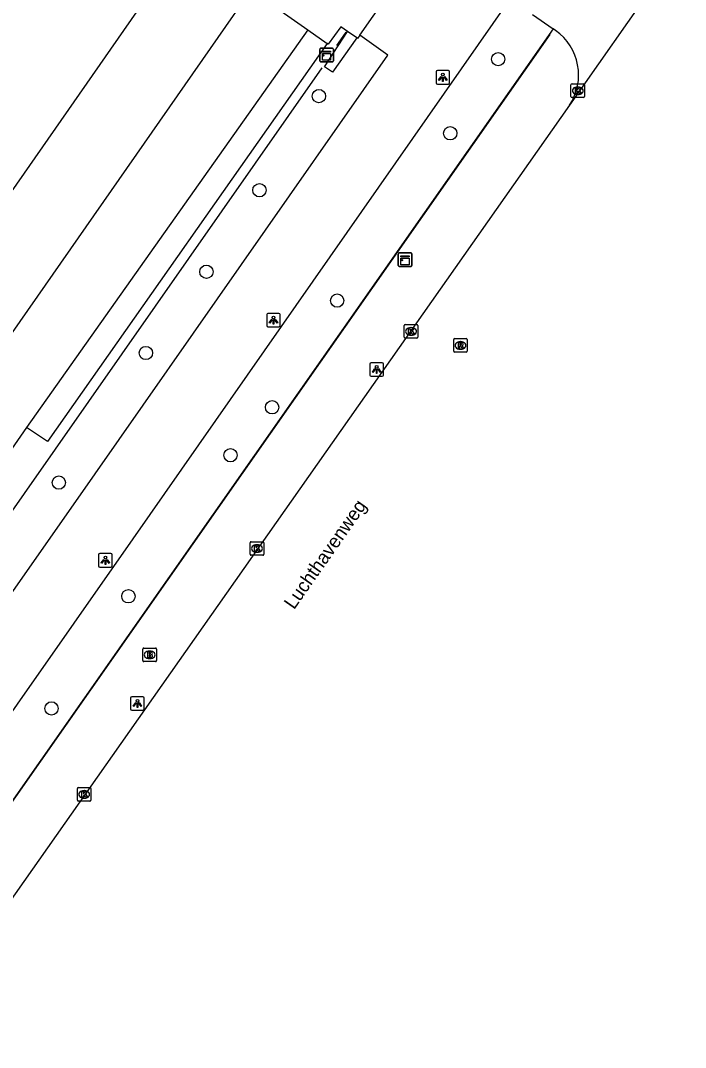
# Model space of a CAD drawing. Extents: x 152881 to 155736, y 382924 to 386919.
# Drawn here: x 155113.9 to 155162.7, y 385052.2 to 385127.6 of the extents above; entities that cross this region are included whole.
import ezdxf

# ---------------------------------------------------------------- set-up
doc = ezdxf.new("R2010")
doc.units = 0
for name, color, linetype in [('IMGEO_Berm_groen', 7, 'Continuous'), ('IMGEO_Boom', 7, 'Continuous'), ('IMGEO_Brandkraan', 7, 'Continuous'), ('IMGEO_Hek', 7, 'Continuous'), ('IMGEO_Kast', 7, 'Continuous'), ('IMGEO_Kolk', 7, 'Continuous'), ('IMGEO_Lichtpunt', 7, 'Continuous'), ('IMGEO_Openbare_ruimte_label', 7, 'Continuous'), ('IMGEO_Parkeervlak_gesloten', 7, 'Continuous'), ('IMGEO_Rijbaan_lokaal_gesloten', 7, 'Continuous'), ('IMGEO_Rijbaan_lokaal_open', 7, 'Continuous'), ('IMGEO_Rioolput', 7, 'Continuous'), ('IMGEO_Voetpad_gesloten', 7, 'Continuous'), ('IMGEO_Voetpad_halfverhard', 7, 'Continuous'), ('IMGEO_Voetpad_open', 7, 'Continuous')]:
    doc.layers.add(name, color=color, linetype=linetype)

msp = doc.modelspace()

# ---------------------------------------------------------------- linework, layer by layer
at = {"layer": 'IMGEO_Berm_groen'}
msp.add_lwpolyline([(155152.981, 385126.958), (155077.878, 385019.794)], dxfattribs=at)
at = {"layer": 'IMGEO_Boom'}
for centre in [(155148.933, 385124.732), (155135.772, 385122.021), (155145.413, 385119.287), (155131.404, 385115.109), (155127.505, 385109.119), (155137.113, 385107.003), (155123.064, 385103.156), (155132.332, 385099.167), (155129.278, 385095.648), (155116.668, 385093.637), (155121.775, 385085.29), (155116.13, 385077.056)]:
    msp.add_circle(centre, 0.489, dxfattribs=at)
at = {"layer": 'IMGEO_Brandkraan'}
for p, q in [((155122.917, 385081.491), (155123.769, 385081.491)), ((155122.842, 385080.565), (155122.842, 385081.417)), ((155123.353, 385080.711), (155123.328, 385080.711)), ((155123.33, 385081.271), (155123.355, 385081.271)), ((155123.843, 385081.417), (155123.843, 385080.565)), ((155123.769, 385080.491), (155122.917, 385080.491))]:
    msp.add_line(p, q, dxfattribs=at)
for points in [[(155122.917, 385081.491), (155123.769, 385081.491)], [(155122.842, 385080.565), (155122.842, 385081.417)], [(155123.19, 385081.191), (155123.19, 385080.791), (155123.403, 385080.791)], [(155123.421, 385081.191), (155123.19, 385081.191)], [(155123.369, 385081.11), (155123.315, 385081.11), (155123.315, 385081.034)], [(155123.315, 385081.034), (155123.368, 385081.034)], [(155123.377, 385080.958), (155123.315, 385080.958), (155123.315, 385080.877)], [(155123.315, 385080.877), (155123.377, 385080.877)], [(155123.843, 385081.417), (155123.843, 385080.565)], [(155123.769, 385080.491), (155122.917, 385080.491)]]:
    msp.add_lwpolyline(points, dxfattribs=at)
for centre, radius, start, end in [((155122.919, 385081.415), 0.0765, 91.55205, 178.44795), ((155122.919, 385081.415), 0.0765, 91.55205, 178.44795), ((155123.767, 385081.415), 0.0765, 1.55205, 88.44795), ((155123.767, 385081.415), 0.0765, 1.55205, 88.44795), ((155123.37, 385081.072), 0.0379, 267.82845, 90.93552), ((155123.378, 385080.917), 0.0404, 269.87594, 90.50774), ((155123.409, 385081.042), 0.251, 268.66757, 293.53466), ((155123.425, 385081.046), 0.145, 59.4692, 91.53667), ((155123.45, 385081.093), 0.0922, 285.51372, 58.15012), ((155123.455, 385080.901), 0.105, 301.31148, 78.98903), ((155122.919, 385080.567), 0.0765, 181.55205, 268.44795), ((155122.919, 385080.567), 0.0765, 181.55205, 268.44795), ((155123.767, 385080.567), 0.0765, 271.55205, 358.44795), ((155123.767, 385080.567), 0.0765, 271.55205, 358.44795)]:
    msp.add_arc(centre, radius, start, end, dxfattribs=at)
for centre, major_axis, ratio, start_param, end_param in [((155123.329, 385080.991), (-0.387, 0.002), 0.722429, 4.712389, 7.853982), ((155123.354, 385080.991), (-0.39, 0.002), 0.717154, 1.570796, 4.712389)]:
    msp.add_ellipse(centre, major_axis=major_axis, ratio=ratio, start_param=start_param, end_param=end_param, dxfattribs=at)
at = {"layer": 'IMGEO_Hek'}
for points in [[(155137.751, 385126.715), (155137.058, 385125.724)], [(155152.718, 385126.532), (155081.57, 385025.069)], [(155094.545, 385064.824), (155135.997, 385124.094)]]:
    msp.add_lwpolyline(points, dxfattribs=at)
at = {"layer": 'IMGEO_Kast'}
for p, q in [((155135.832, 385124.612), (155135.832, 385125.453)), ((155135.832, 385125.453), (155135.832, 385124.612)), ((155135.907, 385125.537), (155136.748, 385125.537)), ((155136.748, 385125.537), (155135.907, 385125.537)), ((155136.832, 385125.462), (155136.832, 385124.621)), ((155136.832, 385124.621), (155136.832, 385125.462)), ((155136.757, 385124.537), (155135.916, 385124.537)), ((155135.916, 385124.537), (155136.757, 385124.537)), ((155141.599, 385109.583), (155141.599, 385110.424)), ((155141.599, 385110.424), (155141.599, 385109.583)), ((155141.674, 385110.508), (155142.515, 385110.508)), ((155142.515, 385110.508), (155141.674, 385110.508)), ((155142.599, 385110.433), (155142.599, 385109.592)), ((155142.599, 385109.592), (155142.599, 385110.433)), ((155142.524, 385109.508), (155141.683, 385109.508)), ((155141.683, 385109.508), (155142.524, 385109.508))]:
    msp.add_line(p, q, dxfattribs=at)
for points in [[(155136.027, 385125.327), (155136.627, 385125.327), (155136.627, 385125.242), (155136.027, 385125.242), (155136.027, 385125.327)], [(155136.027, 385125.152), (155136.627, 385125.152), (155136.627, 385124.663), (155136.027, 385124.663), (155136.027, 385125.152)], [(155141.794, 385110.298), (155142.394, 385110.298), (155142.394, 385110.213), (155141.794, 385110.213), (155141.794, 385110.298)], [(155141.794, 385110.123), (155142.394, 385110.123), (155142.394, 385109.634), (155141.794, 385109.634), (155141.794, 385110.123)]]:
    msp.add_lwpolyline(points, dxfattribs=at)
for centre in [(155136.111, 385125.001), (155141.878, 385109.972)]:
    msp.add_circle(centre, 0.0377, dxfattribs=at)
for centre, start, end in [((155135.91, 385125.459), 92.4484, 184.28452), ((155135.91, 385125.459), 92.4484, 184.28452), ((155136.754, 385125.459), 2.4484, 94.28452), ((155136.754, 385125.459), 2.4484, 94.28452), ((155135.91, 385124.615), 182.4484, 274.28452), ((155135.91, 385124.615), 182.4484, 274.28452), ((155136.754, 385124.615), 272.4484, 4.28452), ((155136.754, 385124.615), 272.4484, 4.28452), ((155141.677, 385110.43), 92.4484, 184.28452), ((155141.677, 385110.43), 92.4484, 184.28452), ((155142.521, 385110.43), 2.4484, 94.28452), ((155142.521, 385110.43), 2.4484, 94.28452), ((155141.677, 385109.586), 182.4484, 274.28452), ((155141.677, 385109.586), 182.4484, 274.28452), ((155142.521, 385109.586), 272.4484, 4.28452), ((155142.521, 385109.586), 272.4484, 4.28452)]:
    msp.add_arc(centre, 0.0779, start, end, dxfattribs=at)
at = {"layer": 'IMGEO_Kolk'}
for p, q in [((155154.283, 385121.991), (155154.283, 385122.843)), ((155154.358, 385122.917), (155155.21, 385122.917)), ((155154.771, 385122.697), (155154.796, 385122.697)), ((155155.284, 385122.843), (155155.284, 385121.991)), ((155155.21, 385121.917), (155154.358, 385121.917)), ((155154.794, 385122.137), (155154.769, 385122.137)), ((155142.036, 385104.313), (155142.036, 385105.165)), ((155142.111, 385105.239), (155142.963, 385105.239)), ((155142.524, 385105.019), (155142.549, 385105.019)), ((155143.037, 385105.165), (155143.037, 385104.313)), ((155142.963, 385104.239), (155142.111, 385104.239)), ((155142.547, 385104.459), (155142.522, 385104.459)), ((155130.72, 385088.374), (155130.72, 385089.226)), ((155130.795, 385089.3), (155131.647, 385089.3)), ((155131.208, 385089.08), (155131.233, 385089.08)), ((155131.721, 385089.226), (155131.721, 385088.374)), ((155131.647, 385088.3), (155130.795, 385088.3)), ((155131.231, 385088.52), (155131.206, 385088.52)), ((155118.029, 385070.319), (155118.029, 385071.171)), ((155118.104, 385071.245), (155118.956, 385071.245)), ((155118.517, 385071.025), (155118.542, 385071.025)), ((155119.03, 385071.171), (155119.03, 385070.319)), ((155118.956, 385070.245), (155118.104, 385070.245)), ((155118.54, 385070.465), (155118.515, 385070.465))]:
    msp.add_line(p, q, dxfattribs=at)
for points in [[(155154.283, 385121.991), (155154.283, 385122.843)], [(155154.358, 385122.917), (155155.21, 385122.917)], [(155154.604, 385122.617), (155154.727, 385122.617), (155154.727, 385122.466), (155154.857, 385122.617), (155155.021, 385122.617), (155154.875, 385122.466), (155155.028, 385122.217), (155154.876, 385122.217), (155154.791, 385122.381), (155154.727, 385122.314), (155154.727, 385122.217), (155154.604, 385122.217), (155154.604, 385122.617)], [(155155.284, 385122.843), (155155.284, 385121.991)], [(155155.21, 385121.917), (155154.358, 385121.917)], [(155142.036, 385104.313), (155142.036, 385105.165)], [(155142.111, 385105.239), (155142.963, 385105.239)], [(155142.357, 385104.939), (155142.48, 385104.939), (155142.48, 385104.788), (155142.61, 385104.939), (155142.774, 385104.939), (155142.628, 385104.788), (155142.781, 385104.539), (155142.629, 385104.539), (155142.544, 385104.703), (155142.48, 385104.636), (155142.48, 385104.539), (155142.357, 385104.539), (155142.357, 385104.939)], [(155143.037, 385105.165), (155143.037, 385104.313)], [(155142.963, 385104.239), (155142.111, 385104.239)], [(155130.72, 385088.374), (155130.72, 385089.226)], [(155130.795, 385089.3), (155131.647, 385089.3)], [(155131.721, 385089.226), (155131.721, 385088.374)], [(155131.647, 385088.3), (155130.795, 385088.3)], [(155131.041, 385089), (155131.164, 385089), (155131.164, 385088.849), (155131.294, 385089), (155131.458, 385089), (155131.312, 385088.849), (155131.465, 385088.6), (155131.313, 385088.6), (155131.228, 385088.764), (155131.164, 385088.697), (155131.164, 385088.6), (155131.041, 385088.6), (155131.041, 385089)], [(155118.029, 385070.319), (155118.029, 385071.171)], [(155118.104, 385071.245), (155118.956, 385071.245)], [(155118.35, 385070.945), (155118.473, 385070.945), (155118.473, 385070.794), (155118.603, 385070.945), (155118.767, 385070.945), (155118.621, 385070.794), (155118.774, 385070.545), (155118.622, 385070.545), (155118.537, 385070.709), (155118.473, 385070.642), (155118.473, 385070.545), (155118.35, 385070.545), (155118.35, 385070.945)], [(155119.03, 385071.171), (155119.03, 385070.319)], [(155118.956, 385070.245), (155118.104, 385070.245)]]:
    msp.add_lwpolyline(points, dxfattribs=at)
for centre, start, end in [((155154.36, 385122.841), 91.55205, 178.44795), ((155154.36, 385122.841), 91.55205, 178.44795), ((155155.208, 385122.841), 1.55205, 88.44795), ((155155.208, 385122.841), 1.55205, 88.44795), ((155154.36, 385121.993), 181.55205, 268.44795), ((155154.36, 385121.993), 181.55205, 268.44795), ((155155.208, 385121.993), 271.55205, 358.44795), ((155155.208, 385121.993), 271.55205, 358.44795), ((155142.113, 385105.163), 91.55205, 178.44795), ((155142.113, 385105.163), 91.55205, 178.44795), ((155142.961, 385105.163), 1.55205, 88.44795), ((155142.961, 385105.163), 1.55205, 88.44795), ((155142.113, 385104.315), 181.55205, 268.44795), ((155142.113, 385104.315), 181.55205, 268.44795), ((155142.961, 385104.315), 271.55205, 358.44795), ((155142.961, 385104.315), 271.55205, 358.44795), ((155130.797, 385089.224), 91.55205, 178.44795), ((155130.797, 385089.224), 91.55205, 178.44795), ((155131.645, 385089.224), 1.55205, 88.44795), ((155131.645, 385089.224), 1.55205, 88.44795), ((155130.797, 385088.376), 181.55205, 268.44795), ((155130.797, 385088.376), 181.55205, 268.44795), ((155131.645, 385088.376), 271.55205, 358.44795), ((155131.645, 385088.376), 271.55205, 358.44795), ((155118.106, 385071.169), 91.55205, 178.44795), ((155118.106, 385071.169), 91.55205, 178.44795), ((155118.954, 385071.169), 1.55205, 88.44795), ((155118.954, 385071.169), 1.55205, 88.44795), ((155118.106, 385070.321), 181.55205, 268.44795), ((155118.106, 385070.321), 181.55205, 268.44795), ((155118.954, 385070.321), 271.55205, 358.44795), ((155118.954, 385070.321), 271.55205, 358.44795)]:
    msp.add_arc(centre, 0.0765, start, end, dxfattribs=at)
for centre, major_axis, ratio, start_param, end_param in [((155154.77, 385122.417), (-0.387, 0.002), 0.722429, 4.712389, 7.853982), ((155154.795, 385122.417), (-0.39, 0.002), 0.717154, 1.570796, 4.712389), ((155142.523, 385104.739), (-0.387, 0.002), 0.722429, 4.712389, 7.853982), ((155142.548, 385104.739), (-0.39, 0.002), 0.717154, 1.570796, 4.712389), ((155131.207, 385088.8), (-0.387, 0.002), 0.722429, 4.712389, 7.853982), ((155131.232, 385088.8), (-0.39, 0.002), 0.717154, 1.570796, 4.712389), ((155118.516, 385070.745), (-0.387, 0.002), 0.722429, 4.712389, 7.853982), ((155118.541, 385070.745), (-0.39, 0.002), 0.717154, 1.570796, 4.712389)]:
    msp.add_ellipse(centre, major_axis=major_axis, ratio=ratio, start_param=start_param, end_param=end_param, dxfattribs=at)
at = {"layer": 'IMGEO_Lichtpunt'}
for p, q in [((155144.376, 385123.804), (155144.376, 385122.997)), ((155144.376, 385123.804), (155144.376, 385122.997)), ((155145.278, 385123.899), (155144.47, 385123.899)), ((155145.278, 385123.899), (155144.47, 385123.899)), ((155145.372, 385122.997), (155145.372, 385123.804)), ((155145.372, 385122.997), (155145.372, 385123.804)), ((155144.47, 385122.903), (155145.278, 385122.903)), ((155144.47, 385122.903), (155145.278, 385122.903)), ((155131.934, 385105.973), (155131.934, 385105.166)), ((155131.934, 385105.973), (155131.934, 385105.166)), ((155132.836, 385106.068), (155132.028, 385106.068)), ((155132.836, 385106.068), (155132.028, 385106.068)), ((155132.93, 385105.166), (155132.93, 385105.973)), ((155132.93, 385105.166), (155132.93, 385105.973)), ((155132.028, 385105.072), (155132.836, 385105.072)), ((155132.028, 385105.072), (155132.836, 385105.072)), ((155139.512, 385102.345), (155139.512, 385101.538)), ((155139.512, 385102.345), (155139.512, 385101.538)), ((155140.414, 385102.44), (155139.606, 385102.44)), ((155140.414, 385102.44), (155139.606, 385102.44)), ((155140.508, 385101.538), (155140.508, 385102.345)), ((155140.508, 385101.538), (155140.508, 385102.345)), ((155139.606, 385101.444), (155140.414, 385101.444)), ((155139.606, 385101.444), (155140.414, 385101.444)), ((155119.588, 385088.336), (155119.588, 385087.529)), ((155119.588, 385088.336), (155119.588, 385087.529)), ((155120.49, 385088.431), (155119.682, 385088.431)), ((155120.49, 385088.431), (155119.682, 385088.431)), ((155120.584, 385087.529), (155120.584, 385088.336)), ((155120.584, 385087.529), (155120.584, 385088.336)), ((155119.682, 385087.435), (155120.49, 385087.435)), ((155119.682, 385087.435), (155120.49, 385087.435)), ((155121.939, 385077.821), (155121.939, 385077.014)), ((155121.939, 385077.821), (155121.939, 385077.014)), ((155122.841, 385077.916), (155122.033, 385077.916)), ((155122.841, 385077.916), (155122.033, 385077.916)), ((155122.935, 385077.014), (155122.935, 385077.821)), ((155122.935, 385077.014), (155122.935, 385077.821)), ((155122.033, 385076.92), (155122.841, 385076.92)), ((155122.033, 385076.92), (155122.841, 385076.92))]:
    msp.add_line(p, q, dxfattribs=at)
for points in [[(155144.75, 385123.468), (155144.789, 385123.44), (155144.601, 385123.178), (155144.563, 385123.205), (155144.75, 385123.468)], [(155144.852, 385123.42), (155144.899, 385123.42), (155144.899, 385123.098), (155144.852, 385123.098), (155144.852, 385123.42)], [(155144.962, 385123.44), (155145, 385123.467), (155145.187, 385123.205), (155145.148, 385123.177), (155144.962, 385123.44)], [(155132.308, 385105.637), (155132.347, 385105.609), (155132.159, 385105.347), (155132.121, 385105.374), (155132.308, 385105.637)], [(155132.52, 385105.609), (155132.558, 385105.636), (155132.745, 385105.374), (155132.706, 385105.346), (155132.52, 385105.609)], [(155132.41, 385105.589), (155132.457, 385105.589), (155132.457, 385105.267), (155132.41, 385105.267), (155132.41, 385105.589)], [(155139.886, 385102.009), (155139.925, 385101.981), (155139.737, 385101.719), (155139.699, 385101.746), (155139.886, 385102.009)], [(155139.988, 385101.961), (155140.035, 385101.961), (155140.035, 385101.639), (155139.988, 385101.639), (155139.988, 385101.961)], [(155140.098, 385101.981), (155140.136, 385102.008), (155140.323, 385101.746), (155140.284, 385101.718), (155140.098, 385101.981)], [(155119.962, 385088), (155120.001, 385087.972), (155119.813, 385087.71), (155119.775, 385087.737), (155119.962, 385088)], [(155120.064, 385087.952), (155120.111, 385087.952), (155120.111, 385087.63), (155120.064, 385087.63), (155120.064, 385087.952)], [(155120.174, 385087.972), (155120.212, 385087.999), (155120.399, 385087.737), (155120.36, 385087.709), (155120.174, 385087.972)], [(155122.313, 385077.485), (155122.352, 385077.457), (155122.164, 385077.195), (155122.126, 385077.222), (155122.313, 385077.485)], [(155122.415, 385077.437), (155122.462, 385077.437), (155122.462, 385077.115), (155122.415, 385077.115), (155122.415, 385077.437)], [(155122.525, 385077.457), (155122.563, 385077.484), (155122.75, 385077.222), (155122.711, 385077.194), (155122.525, 385077.457)]]:
    msp.add_lwpolyline(points, dxfattribs=at)
for centre in [(155144.875, 385123.602), (155132.433, 385105.771), (155140.011, 385102.143), (155120.087, 385088.134), (155122.438, 385077.619)]:
    msp.add_circle(centre, 0.0994, dxfattribs=at)
for centre, start, end in [((155144.47, 385123.804), 90, 180), ((155144.47, 385123.804), 90, 180), ((155145.278, 385123.804), 0, 90), ((155145.278, 385123.804), 0, 90), ((155144.47, 385122.997), 180, 270), ((155144.47, 385122.997), 180, 270), ((155145.278, 385122.997), 270, 0), ((155145.278, 385122.997), 270, 360), ((155132.028, 385105.973), 90, 180), ((155132.028, 385105.973), 90, 180), ((155132.836, 385105.973), 0, 90), ((155132.836, 385105.973), 0, 90), ((155132.028, 385105.166), 180, 270), ((155132.028, 385105.166), 180, 270), ((155132.836, 385105.166), 270, 0), ((155132.836, 385105.166), 270, 360), ((155139.606, 385102.345), 90, 180), ((155139.606, 385102.345), 90, 180), ((155140.414, 385102.345), 0, 90), ((155140.414, 385102.345), 0, 90), ((155139.606, 385101.538), 180, 270), ((155139.606, 385101.538), 180, 270), ((155140.414, 385101.538), 270, 0), ((155140.414, 385101.538), 270, 360), ((155119.682, 385088.336), 90, 180), ((155119.682, 385088.336), 90, 180), ((155120.49, 385088.336), 0, 90), ((155120.49, 385088.336), 0, 90), ((155119.682, 385087.529), 180, 270), ((155119.682, 385087.529), 180, 270), ((155120.49, 385087.529), 270, 0), ((155120.49, 385087.529), 270, 360), ((155122.033, 385077.821), 90, 180), ((155122.033, 385077.821), 90, 180), ((155122.841, 385077.821), 0, 90), ((155122.841, 385077.821), 0, 90), ((155122.033, 385077.014), 180, 270), ((155122.033, 385077.014), 180, 270), ((155122.841, 385077.014), 270, 0), ((155122.841, 385077.014), 270, 360)]:
    msp.add_arc(centre, 0.0946, start, end, dxfattribs=at)
at = {"layer": 'IMGEO_Parkeervlak_gesloten'}
msp.add_lwpolyline([(155114.286, 385097.692), (155092.417, 385066.08)], dxfattribs=at)
at = {"layer": 'IMGEO_Rijbaan_lokaal_gesloten'}
for points in [[(155122.384, 385128.218), (155064.639, 385045.363), (155055.69, 385051.841), (155114.227, 385134.027), (155122.384, 385128.218)], [(155162.691, 385133.521), (155154.185, 385121.353)], [(155073.777, 385039.153), (155069.621, 385042.093), (155130.791, 385129.812)], [(155154.185, 385121.353), (155094.269, 385036.176)]]:
    msp.add_lwpolyline(points, dxfattribs=at)
at = {"layer": 'IMGEO_Rijbaan_lokaal_open'}
for points in [[(155151.449, 385128.02), (155152.981, 385126.958)], [(155153.147, 385126.843), (155152.981, 385126.958)]]:
    msp.add_lwpolyline(points, dxfattribs=at)
msp.add_arc((155150.811, 385123.558), 4.031, 326.83201, 54.58117, dxfattribs=at)
at = {"layer": 'IMGEO_Rioolput'}
for p, q in [((155145.667, 385103.288), (155145.667, 385104.14)), ((155145.742, 385104.214), (155146.594, 385104.214)), ((155146.668, 385104.14), (155146.668, 385103.288)), ((155146.178, 385103.434), (155146.153, 385103.434)), ((155146.155, 385103.994), (155146.18, 385103.994)), ((155146.594, 385103.214), (155145.742, 385103.214))]:
    msp.add_line(p, q, dxfattribs=at)
for points in [[(155145.667, 385103.288), (155145.667, 385104.14)], [(155145.742, 385104.214), (155146.594, 385104.214)], [(155146.668, 385104.14), (155146.668, 385103.288)], [(155146.256, 385103.912), (155146.004, 385103.914), (155146.004, 385103.514)], [(155146.004, 385103.514), (155146.128, 385103.514), (155146.128, 385103.676), (155146.139, 385103.676)], [(155146.182, 385103.833), (155146.128, 385103.833), (155146.128, 385103.752)], [(155146.128, 385103.752), (155146.18, 385103.752)], [(155146.186, 385103.647), (155146.257, 385103.514), (155146.397, 385103.514), (155146.332, 385103.64)], [(155146.594, 385103.214), (155145.742, 385103.214)]]:
    msp.add_lwpolyline(points, dxfattribs=at)
for centre, radius, start, end in [((155145.744, 385104.138), 0.0765, 91.55205, 178.44795), ((155145.744, 385104.138), 0.0765, 91.55205, 178.44795), ((155146.592, 385104.138), 0.0765, 1.55205, 88.44795), ((155146.592, 385104.138), 0.0765, 1.55205, 88.44795), ((155146.138, 385103.623), 0.0533, 26.02933, 88.69889), ((155146.164, 385103.941), 0.19, 274.7715, 282.96867), ((155146.188, 385103.737), 0.0964, 77.00612, 93.18647), ((155146.202, 385103.794), 0.0378, 276.66336, 79.67722), ((155146.255, 385103.802), 0.109, 350.36119, 89.41601), ((155146.253, 385103.802), 0.112, 277.58423, 350.98172), ((155146.237, 385103.587), 0.108, 29.51342, 73.79051), ((155145.744, 385103.29), 0.0765, 181.55205, 268.44795), ((155145.744, 385103.29), 0.0765, 181.55205, 268.44795), ((155146.592, 385103.29), 0.0765, 271.55205, 358.44795), ((155146.592, 385103.29), 0.0765, 271.55205, 358.44795)]:
    msp.add_arc(centre, radius, start, end, dxfattribs=at)
for centre, major_axis, ratio, start_param, end_param in [((155146.154, 385103.714), (-0.387, 0.002), 0.722429, 4.712389, 7.853982), ((155146.179, 385103.714), (-0.39, 0.002), 0.717154, 1.570796, 4.712389)]:
    msp.add_ellipse(centre, major_axis=major_axis, ratio=ratio, start_param=start_param, end_param=end_param, dxfattribs=at)
at = {"layer": 'IMGEO_Voetpad_gesloten'}
for points in [[(155138.78, 385126.487), (155141.884, 385130.945), (155140.654, 385131.804), (155141.958, 385133.681)], [(155149.799, 385129.158), (155122.102, 385089.512), (155100.747, 385059.032), (155084.654, 385036.053), (155074.437, 385021.508)], [(155134.953, 385126.884), (155114.286, 385097.692)], [(155134.953, 385126.884), (155136.365, 385125.891)], [(155092.417, 385066.08), (155097.228, 385062.738), (155119.33, 385094.281), (155140.82, 385125.037), (155138.78, 385126.487)], [(155136.365, 385125.891), (155115.831, 385096.645), (155114.286, 385097.692)]]:
    msp.add_lwpolyline(points, dxfattribs=at)
at = {"layer": 'IMGEO_Voetpad_halfverhard'}
msp.add_lwpolyline([(155138.545, 385126.297), (155136.764, 385123.788), (155136.172, 385124.179), (155137.878, 385126.764)], dxfattribs=at)
at = {"layer": 'IMGEO_Voetpad_open'}
for points in [[(155130.791, 385129.812), (155134.953, 385126.884)], [(155137.878, 385126.764), (155137.372, 385127.118), (155136.457, 385125.827), (155136.365, 385125.891)], [(155138.545, 385126.297), (155137.878, 385126.764)], [(155138.78, 385126.487), (155138.614, 385126.249), (155138.545, 385126.297)]]:
    msp.add_lwpolyline(points, dxfattribs=at)

# ---------------------------------------------------------------- texts
at = {"layer": 'IMGEO_Openbare_ruimte_label'}
msp.add_text('Luchthavenweg', height=1, rotation=55.0549, dxfattribs=at).set_placement((155133.945, 385084.262))

doc.saveas('drawing.dxf')
